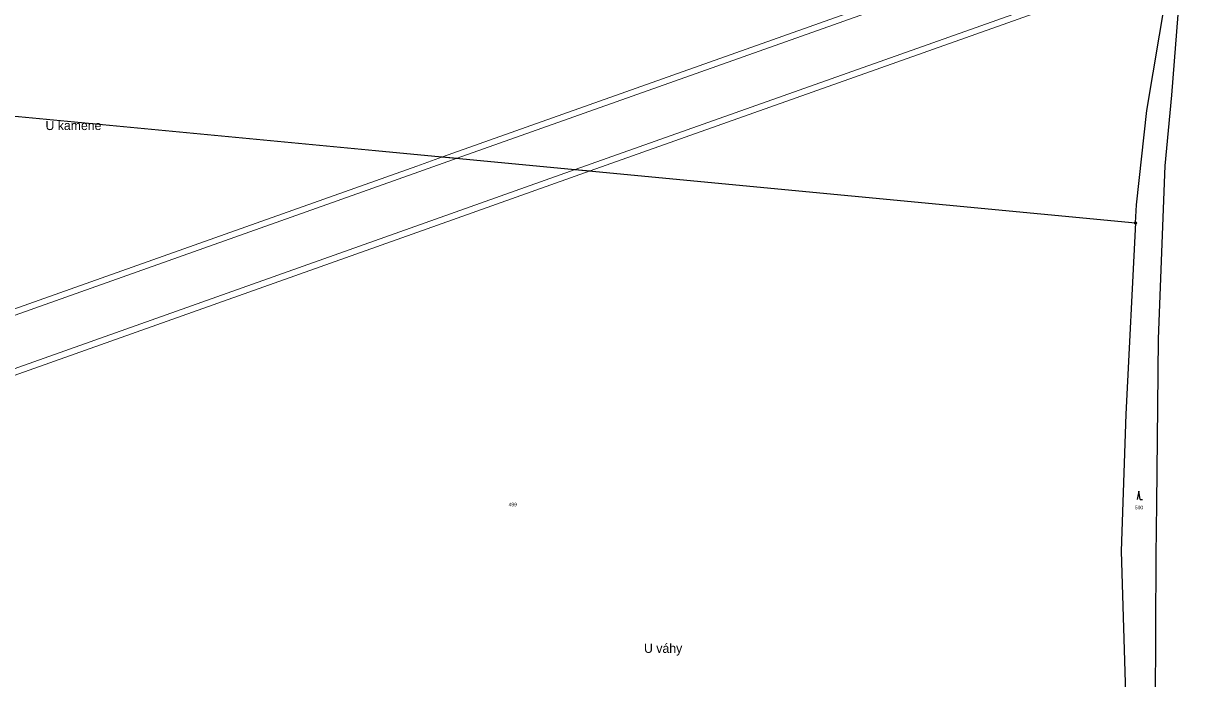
# Model space of a CAD drawing. Extents: x -759947 to -757003, y -1019641 to -1017100.
# Drawn here: x -757716 to -757157, y -1018437 to -1018123 of the extents above; entities that cross this region are included whole.
import ezdxf
from ezdxf.enums import TextEntityAlignment as Align

# ---------------------------------------------------------------- set-up
doc = ezdxf.new("R2010")
doc.units = 0
doc.header["$LTSCALE"] = 0.68
for name, color, linetype, lineweight in [('1', 7, 'Continuous', 25), ('13', 7, 'Continuous', 13), ('3', 7, 'Continuous', 25), ('7', 7, 'Continuous', 13), ('8', 7, 'Continuous', 25)]:
    doc.layers.add(name, color=color, linetype=linetype, lineweight=lineweight)
doc.layers.add('2', color=7, linetype='Continuous')

msp = doc.modelspace()

# ---------------------------------------------------------------- linework, layer by layer
at = {"layer": '1'}
for p, q in [((-757156.67, -1018045.29), (-757165.43, -1018157.03)), ((-757177.21, -1018164.41), (-757164.09, -1018086.85)), ((-757165.43, -1018157.03), (-757168.61, -1018191)), ((-757729.88, -1018166.17), (-757547.11, -1018183.6)), ((-757182.19, -1018209.67), (-757177.21, -1018164.41)), ((-757547.11, -1018183.6), (-757364.34, -1018201.03)), ((-757168.61, -1018191), (-757171.77, -1018273.9)), ((-757364.34, -1018201.03), (-757182.63, -1018218.36)), ((-757182.63, -1018218.36), (-757182.19, -1018209.67)), ((-757182.63, -1018218.36), (-757187.32, -1018310)), ((-757171.77, -1018273.9), (-757172.11, -1018306.34)), ((-757172.11, -1018306.34), (-757172.61, -1018352.83)), ((-757187.32, -1018310), (-757189.58, -1018375.77)), ((-757172.61, -1018352.83), (-757172.87, -1018377.78)), ((-757189.58, -1018375.77), (-757185.3, -1018517.43)), ((-757172.87, -1018377.78), (-757173.32, -1018460.95))]:
    msp.add_line(p, q, dxfattribs=at)
at = {"layer": '13'}
for points in [[(-757170.97, -1018064.6), (-757515.01, -1018186.66), (-757507.94, -1018187.34), (-757169.97, -1018067.4), (-757167.05, -1018066.36), (-757165.16, -1018062.53)], [(-757164.79, -1018091.02), (-757451.37, -1018192.73), (-757444.3, -1018193.4), (-757165.37, -1018094.44)], [(-757515.01, -1018186.66), (-757527.43, -1018191.07), (-757825.43, -1018296.8), (-757825.99, -1018300.19), (-757526.44, -1018193.9), (-757507.94, -1018187.34)], [(-757451.37, -1018192.73), (-757518.48, -1018216.55), (-757830.49, -1018327.25), (-757831.05, -1018330.62), (-757517.49, -1018219.37), (-757444.3, -1018193.4)]]:
    msp.add_lwpolyline(points, close=True, dxfattribs=at)
at = {"layer": '3'}
msp.add_line((-757180.35, -1018350.96), (-757179.354, -1018350.96), dxfattribs=at)
msp.add_lwpolyline([(-757180.35, -1018350.96), (-757181.1, -1018346.96), (-757181.85, -1018350.96)], dxfattribs=at)
at = {"layer": '8'}
for radius in [0.5, 0.0303]:
    msp.add_circle((-757182.63, -1018218.3599), radius, dxfattribs=at)

# ---------------------------------------------------------------- texts
at = {"layer": '2'}
for s, p in [('499', (-757483.33, -1018354.225)), ('500', (-757182.9, -1018355.665))]:
    msp.add_text(s, height=1.7, dxfattribs=at).set_placement(p)
at = {"layer": '7'}
for s, p in [('U kamene', (-757692.06, -1018173.8)), ('U váhy', (-757409.219, -1018424.52))]:
    msp.add_text(s, height=4.4, dxfattribs=at).set_placement(p, align=Align.CENTER)

doc.saveas('drawing.dxf')
